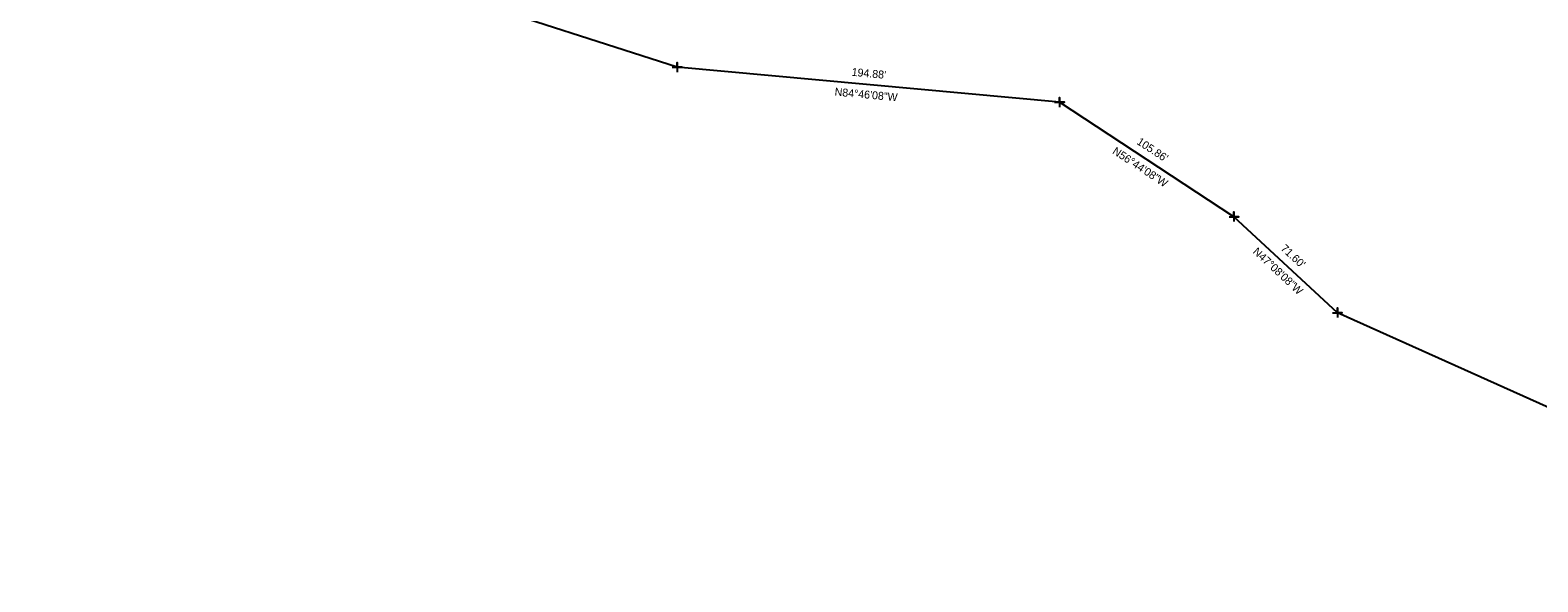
# Model space of a CAD drawing. Extents: x 1121294 to 1124558, y 901107 to 903080.
# Drawn here: x 1121297 to 1122062, y 901988 to 902268 of the extents above; entities that cross this region are included whole.
import ezdxf

# ---------------------------------------------------------------- set-up
doc = ezdxf.new("R2010")
doc.units = 0
for name, color, linetype in [('CTL Secondary Horizontal and Vertical CELL', 7, 'Continuous'), ('CTL Vertical Benchmark CELL', 7, 'Continuous'), ('Exist Survey Observation Group', 7, 'Continuous')]:
    doc.layers.add(name, color=color, linetype=linetype)

msp = doc.modelspace()

# ---------------------------------------------------------------- linework, layer by layer
at = {"layer": 'CTL Secondary Horizontal and Vertical CELL'}
for p, q in [((1121625.33, 902249.32), (1121296.97, 902355.58)), ((1121819.4, 902231.55), (1121625.33, 902249.32)), ((1121907.91, 902173.49), (1121819.4, 902231.55)), ((1121960.39, 902124.78), (1121907.91, 902173.49)), ((1122264.46, 901988.25), (1121960.39, 902124.78))]:
    msp.add_line(p, q, dxfattribs=at)
at = {"layer": 'CTL Vertical Benchmark CELL'}
for p, q in [((1121625.33, 902249.32), (1121625.33, 902249.32)), ((1121819.4, 902231.55), (1121819.4, 902231.55)), ((1121907.91, 902173.49), (1121907.91, 902173.49)), ((1121960.39, 902124.78), (1121960.39, 902124.78))]:
    msp.add_line(p, q, dxfattribs=at)
for points in [[(1121622.83, 902249.32), (1121627.83, 902249.32), (1121625.33, 902249.32), (1121625.33, 902251.82), (1121625.33, 902246.82)], [(1121816.9, 902231.55), (1121821.9, 902231.55), (1121819.4, 902231.55), (1121819.4, 902234.05), (1121819.4, 902229.05)], [(1121905.41, 902173.49), (1121910.41, 902173.49), (1121907.91, 902173.49), (1121907.91, 902175.99), (1121907.91, 902170.99)], [(1121957.89, 902124.78), (1121962.89, 902124.78), (1121960.39, 902124.78), (1121960.39, 902127.28), (1121960.39, 902122.28)]]:
    msp.add_lwpolyline(points, dxfattribs=at)

# ---------------------------------------------------------------- texts
at = {"layer": 'Exist Survey Observation Group'}
for s, rotation, p in [("194.88'", 354.76897, (1121713.75, 902245.02)), ('N84°46\'08"W', 354.76897, (1121705.12, 902234.97)), ("105.86'", 326.73564, (1121858.21, 902210.61)), ('N56°44\'08"W', 326.73564, (1121845.86, 902205.8)), ('N47°08\'08"W', 317.13564, (1121917.16, 902155.33)), ("71.60'", 317.13564, (1121931.28, 902156.96))]:
    msp.add_text(s, height=4.02, rotation=rotation, dxfattribs=at).set_placement(p)

doc.saveas('drawing.dxf')
